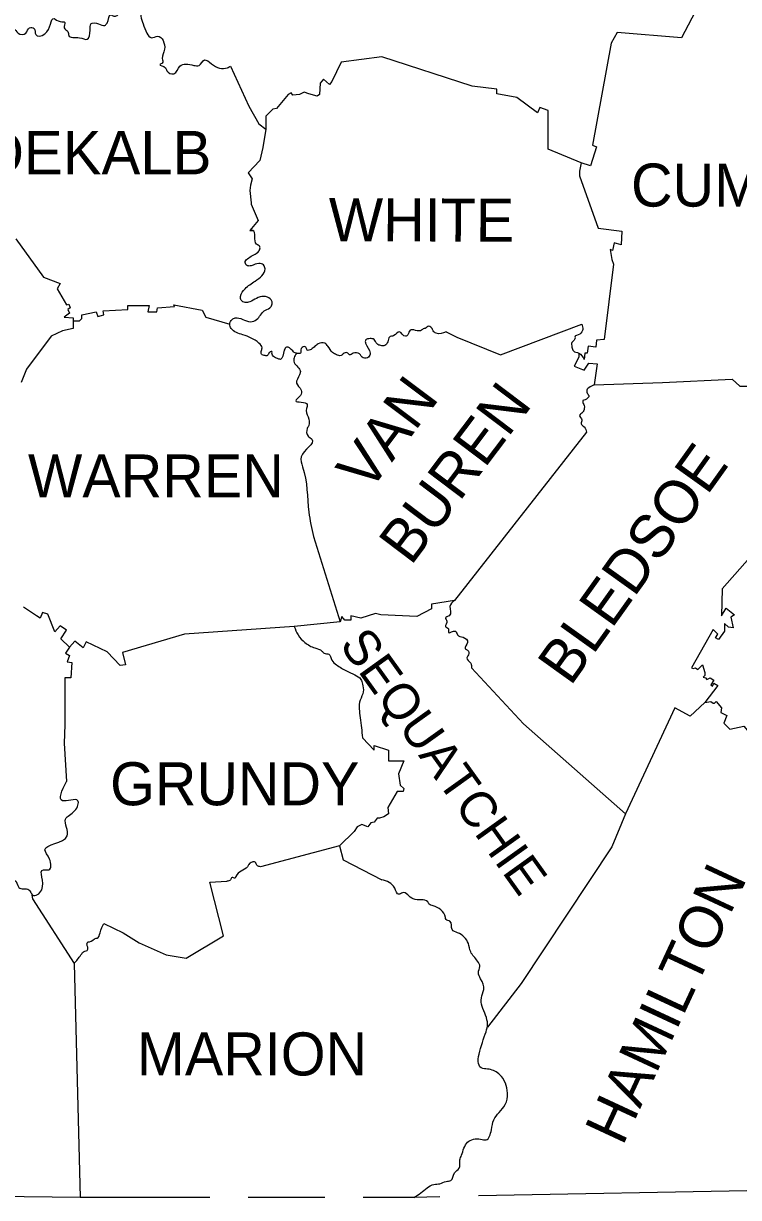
# Model space of a CAD drawing. Extents: x 1577619 to 1828281, y 483481 to 598136.
# Drawn here: x 1705140 to 1707004, y 529328 to 532387 of the extents above; entities that cross this region are included whole.
import ezdxf

# ---------------------------------------------------------------- set-up
doc = ezdxf.new("R2010")
doc.units = 0
doc.layers.add('DESIGN - SHEET - Corner Text', color=7, linetype='Continuous')
doc.layers.add('DESIGN - SHEET - Linework', color=7, linetype='Continuous')

msp = doc.modelspace()

# ---------------------------------------------------------------- linework, layer by layer
at = {"layer": 'DESIGN - SHEET - Linework'}
for p, q in [((1707176.2, 529347.6), (1706326.2, 529331.6)), ((1705926.2, 529327.6), (1705726.2, 529327.6))]:
    msp.add_line(p, q, dxfattribs=at)
for points in [[(1706900.2, 532433.6), (1706856.2, 532349.6), (1706688.2, 532363.6), (1706672.2, 532335.6), (1706624.2, 532069.6), (1706634.2, 532065.6), (1706618.2, 532015.6), (1706594.2, 532023.6), (1706508.2, 532059.6), (1706508.2, 532159.6), (1706486.2, 532167.6), (1706480.2, 532153.6), (1706426.2, 532193.6), (1706374.2, 532203.6), (1706374.2, 532215.6), (1706310.2, 532223.6), (1706074.2, 532299.6), (1705968.2, 532285.6), (1705944.2, 532235.6), (1705938.2, 532227.6), (1705922.2, 532241.6), (1705914.2, 532231.6), (1705912.2, 532201.6), (1705906.2, 532197.6), (1705884.2, 532203.6), (1705872.2, 532207.6), (1705860.2, 532201.6), (1705842.2, 532199.6), (1705838.2, 532205.6), (1705830.2, 532201.6), (1705800.2, 532165.6), (1705790.2, 532163.6), (1705772.2, 532145.6), (1705772.2, 532111.6), (1705764.2, 532063.6), (1705756.2, 532029.6), (1705726.2, 531997.6), (1705736.2, 531981.6), (1705732.2, 531965.6), (1705730.2, 531951.6), (1705734.2, 531919.6), (1705734.2, 531915.6), (1705752.2, 531873.6), (1705730.2, 531847.6), (1705738.2, 531847.6)], [(1705680.2, 532275.6), (1705728.2, 532171.6), (1705754.2, 532125.6), (1705772.2, 532111.6)], [(1706594.2, 532023.6), (1706590.2, 532001.6), (1706590.2, 531989.6), (1706638.2, 531853.6), (1706700.2, 531845.6), (1706698.2, 531809.6), (1706680.2, 531815.6), (1706676.2, 531795.6), (1706670.2, 531797.6), (1706674.2, 531771.6), (1706678.2, 531759.6), (1706654.2, 531563.6), (1706634.2, 531561.6), (1706632.2, 531543.6), (1706612.2, 531545.6), (1706610.2, 531527.6), (1706604.2, 531527.6), (1706602.2, 531511.6)], [(1705120.2, 531825.6), (1705192.2, 531725.6), (1705236.2, 531709.6), (1705228.2, 531695.6), (1705252.2, 531653.6), (1705258.2, 531655.6), (1705262.2, 531645.6), (1705256.2, 531641.6), (1705260.2, 531631.6), (1705246.2, 531621.6), (1705270.2, 531619.6), (1705270.2, 531591.6), (1705242.2, 531585.6), (1705212.2, 531571.6), (1705148.2, 531485.6), (1705134.2, 531451.6)], [(1705270.2, 531611.6), (1705286.2, 531611.6), (1705292.2, 531617.6), (1705292.2, 531627.6), (1705330.2, 531635.6), (1705334.2, 531623.6), (1705350.2, 531627.6), (1705348.2, 531637.6), (1705412.2, 531641.6), (1705412.2, 531651.6), (1705468.2, 531651.6), (1705464.2, 531635.6), (1705488.2, 531635.6), (1705490.2, 531645.6), (1705534.2, 531649.6), (1705532.2, 531653.6), (1705606.2, 531639.6), (1705616.2, 531621.6), (1705678.2, 531603.6)], [(1706242.2, 531583.6), (1706270.2, 531569.6), (1706384.2, 531523.6), (1706596.2, 531603.6)], [(1706588.2, 531525.6), (1706588.2, 531517.6), (1706576.2, 531493.6), (1706602.2, 531483.6), (1706614.2, 531501.6), (1706636.2, 531499.6), (1706628.2, 531445.6), (1706806.2, 531451.6), (1706988.2, 531459.6), (1707008.2, 531441.6), (1707038.2, 531441.6), (1707050.2, 531461.6), (1707098.2, 531461.6), (1707112.2, 531475.6), (1707130.2, 531431.6), (1707126.2, 531429.6), (1707132.2, 531399.6), (1707416.2, 531483.6), (1707456.2, 531495.6), (1707646.2, 531621.6), (1707654.2, 531625.6), (1707690.2, 531625.6)], [(1706608.2, 531321.6), (1706264.2, 530883.6)], [(1707126.2, 531099.6), (1706962.2, 530913.6), (1706960.2, 530843.6), (1706972.2, 530863.6), (1706994.2, 530845.6), (1706984.2, 530839.6), (1706990.2, 530811.6), (1706978.2, 530813.6), (1706968.2, 530823.6), (1706968.2, 530803.6), (1706952.2, 530781.6), (1706944.2, 530785.6), (1706950.2, 530795.6), (1706938.2, 530807.6), (1706882.2, 530707.6), (1706886.2, 530705.6), (1706892.2, 530707.6), (1706898.2, 530703.6), (1706910.2, 530715.6), (1706910.2, 530715.6), (1706916.2, 530695.6), (1706916.2, 530687.6), (1706912.2, 530683.6), (1706918.2, 530681.6), (1706922.2, 530677.6), (1706930.2, 530681.6), (1706940.2, 530675.6), (1706932.2, 530663.6), (1706936.2, 530659.6), (1706940.2, 530667.6), (1706950.2, 530661.6), (1706916.2, 530617.6), (1706878.2, 530581.6), (1706838.2, 530603.6), (1706710.2, 530327.6), (1706674.2, 530241.6), (1706438.2, 529885.6), (1706350.2, 529771.6)], [(1705896.2, 531049.6), (1705966.2, 530827.6)], [(1705260.2, 530761.6), (1705238.2, 530783.6), (1705252.2, 530805.6), (1705236.2, 530817.6), (1705222.2, 530801.6), (1705204.2, 530847.6), (1705190.2, 530851.6), (1705184.2, 530837.6), (1705174.2, 530843.6), (1705140.2, 530865.6)], [(1706264.2, 530883.6), (1706204.2, 530873.6), (1706204.2, 530861.6), (1706166.2, 530841.6), (1706072.2, 530845.6), (1706058.2, 530849.6), (1706020.2, 530837.6), (1705994.2, 530843.6), (1705994.2, 530831.6), (1705978.2, 530831.6), (1705970.2, 530841.6), (1705966.2, 530827.6), (1705846.2, 530815.6), (1705560.2, 530795.6), (1705398.2, 530747.6), (1705406.2, 530715.6), (1705392.2, 530713.6), (1705358.2, 530749.6), (1705304.2, 530775.6), (1705296.2, 530759.6), (1705274.2, 530777.6), (1705260.2, 530761.6), (1705250.2, 530745.6), (1705260.2, 530739.6), (1705254.2, 530723.6), (1705266.2, 530721.6), (1705264.2, 530681.6), (1705248.2, 530681.6), (1705248.2, 530559.6), (1705246.2, 530511.6), (1705252.2, 530411.6)], [(1706308.2, 530707.6), (1706444.2, 530561.6), (1706710.2, 530327.6)], [(1706916.2, 530617.6), (1706932.2, 530619.6), (1706938.2, 530615.6), (1706942.2, 530615.6), (1706946.2, 530619.6), (1706960.2, 530603.6), (1706958.2, 530591.6), (1706974.2, 530583.6), (1706966.2, 530563.6), (1706982.2, 530547.6), (1707018.2, 530555.6), (1707032.2, 530539.6), (1707028.2, 530531.6), (1707038.2, 530529.6), (1707040.2, 530539.6), (1707050.2, 530533.6), (1707066.2, 530551.6), (1707170.2, 530485.6)], [(1706024.2, 530525.6), (1706054.2, 530493.6), (1706054.2, 530505.6), (1706092.2, 530493.6), (1706092.2, 530465.6), (1706132.2, 530465.6), (1706118.2, 530431.6), (1706122.2, 530401.6), (1706132.2, 530393.6), (1706130.2, 530385.6), (1706114.2, 530385.6), (1706090.2, 530343.6), (1706092.2, 530327.6), (1706080.2, 530319.6), (1706068.2, 530315.6), (1706062.2, 530315.6), (1706054.2, 530305.6), (1706046.2, 530303.6), (1706038.2, 530293.6), (1706022.2, 530299.6), (1706010.2, 530293.6), (1706002.2, 530281.6), (1705964.2, 530243.6), (1705758.2, 530189.6)], [(1705964.2, 530243.6), (1705974.2, 530207.6), (1706074.2, 530155.6)], [(1705350.2, 530041.6), (1705400.2, 530017.6), (1705442.2, 529991.6), (1705512.2, 529959.6), (1705564.2, 529951.6), (1705662.2, 530009.6), (1705626.2, 530149.6), (1705670.2, 530151.6)], [(1705162.2, 530115.6), (1705164.2, 530105.6), (1705272.2, 529937.6), (1705288.2, 529327.6)], [(1705626.2, 529327.6), (1705288.2, 529327.6), (1704776.2, 529333.6)], [(1706226.2, 529329.6), (1706158.2, 529327.6), (1706026.2, 529327.6)]]:
    msp.add_lwpolyline(points, dxfattribs=at)
for points in [[(1704876.2, 532331.6), (1704882.2, 532337.6), (1704892.2, 532337.6), (1704918.2, 532321.6), (1704938.2, 532321.6), (1704952.2, 532321.6), (1704964.2, 532321.6), (1704980.2, 532317.6), (1704992.2, 532331.6), (1705004.2, 532315.6), (1705012.2, 532315.6), (1705024.2, 532331.6), (1705034.2, 532323.6), (1705066.2, 532343.6), (1705104.2, 532373.6), (1705114.2, 532373.6), (1705126.2, 532361.6), (1705146.2, 532361.6), (1705156.2, 532375.6), (1705168.2, 532373.6), (1705172.2, 532357.6), (1705196.2, 532359.6), (1705220.2, 532399.6), (1705236.2, 532391.6), (1705248.2, 532389.6), (1705246.2, 532375.6), (1705256.2, 532365.6), (1705258.2, 532355.6), (1705286.2, 532349.6), (1705306.2, 532345.6), (1705314.2, 532369.6), (1705316.2, 532385.6), (1705336.2, 532385.6), (1705352.2, 532381.6), (1705358.2, 532387.6), (1705368.2, 532409.6), (1705376.2, 532405.6), (1705384.2, 532407.6), (1705392.2, 532417.6), (1705410.2, 532429.6), (1705428.2, 532423.6), (1705444.2, 532415.6), (1705446.2, 532405.6), (1705452.2, 532385.6), (1705462.2, 532361.6), (1705474.2, 532349.6), (1705490.2, 532353.6), (1705508.2, 532319.6), (1705502.2, 532295.6), (1705502.2, 532283.6), (1705496.2, 532279.6), (1705510.2, 532271.6), (1705514.2, 532263.6), (1705532.2, 532255.6), (1705548.2, 532275.6), (1705584.2, 532277.6), (1705598.2, 532277.6), (1705612.2, 532291.6), (1705630.2, 532281.6), (1705672.2, 532271.6), (1705680.2, 532275.6)], [(1706242.2, 531583.6), (1706216.2, 531579.6), (1706208.2, 531585.6), (1706204.2, 531593.6), (1706194.2, 531597.6), (1706190.2, 531593.6), (1706180.2, 531589.6), (1706178.2, 531587.6), (1706148.2, 531587.6), (1706142.2, 531575.6), (1706136.2, 531571.6), (1706120.2, 531583.6), (1706106.2, 531573.6), (1706094.2, 531569.6), (1706090.2, 531557.6), (1706082.2, 531547.6), (1706072.2, 531547.6), (1706062.2, 531551.6), (1706054.2, 531563.6), (1706044.2, 531565.6), (1706032.2, 531561.6), (1706032.2, 531553.6), (1706044.2, 531527.6), (1706040.2, 531517.6), (1706026.2, 531515.6), (1706016.2, 531525.6), (1706000.2, 531527.6), (1705990.2, 531523.6), (1705986.2, 531527.6), (1705976.2, 531527.6), (1705968.2, 531521.6), (1705956.2, 531523.6), (1705946.2, 531529.6), (1705934.2, 531545.6), (1705926.2, 531553.6), (1705908.2, 531551.6), (1705900.2, 531545.6), (1705890.2, 531537.6), (1705880.2, 531535.6), (1705876.2, 531543.6), (1705864.2, 531539.6), (1705862.2, 531527.6), (1705852.2, 531527.6), (1705846.2, 531529.6), (1705842.2, 531533.6), (1705826.2, 531543.6), (1705820.2, 531535.6), (1705810.2, 531511.6), (1705802.2, 531513.6), (1705788.2, 531527.6), (1705788.2, 531531.6), (1705782.2, 531529.6), (1705776.2, 531521.6), (1705768.2, 531521.6), (1705762.2, 531523.6), (1705760.2, 531531.6), (1705762.2, 531541.6), (1705754.2, 531553.6), (1705712.2, 531575.6), (1705682.2, 531591.6), (1705678.2, 531603.6), (1705684.2, 531615.6), (1705692.2, 531619.6), (1705732.2, 531609.6), (1705748.2, 531615.6), (1705768.2, 531637.6), (1705782.2, 531645.6), (1705788.2, 531653.6), (1705788.2, 531663.6), (1705776.2, 531673.6), (1705766.2, 531675.6), (1705730.2, 531661.6), (1705718.2, 531659.6), (1705708.2, 531665.6), (1705706.2, 531675.6), (1705718.2, 531695.6), (1705744.2, 531715.6), (1705770.2, 531747.6), (1705766.2, 531757.6), (1705754.2, 531761.6), (1705734.2, 531755.6), (1705724.2, 531755.6), (1705718.2, 531763.6), (1705724.2, 531773.6), (1705750.2, 531789.6), (1705756.2, 531797.6), (1705756.2, 531805.6), (1705748.2, 531811.6), (1705738.2, 531847.6), (1705730.2, 531847.6)], [(1706596.2, 531603.6), (1706598.2, 531589.6), (1706596.2, 531583.6), (1706582.2, 531573.6), (1706578.2, 531571.6), (1706578.2, 531567.6), (1706574.2, 531559.6), (1706570.2, 531555.6), (1706570.2, 531543.6), (1706574.2, 531533.6), (1706588.2, 531527.6), (1706602.2, 531511.6)], [(1705852.2, 531527.6), (1705846.2, 531515.6), (1705846.2, 531503.6), (1705862.2, 531479.6), (1705860.2, 531471.6), (1705852.2, 531449.6), (1705864.2, 531431.6), (1705862.2, 531417.6), (1705850.2, 531403.6), (1705880.2, 531393.6), (1705878.2, 531383.6), (1705882.2, 531361.6), (1705884.2, 531339.6), (1705880.2, 531331.6), (1705882.2, 531311.6), (1705892.2, 531303.6), (1705864.2, 531257.6), (1705868.2, 531231.6), (1705884.2, 531113.6), (1705896.2, 531049.6)], [(1706628.2, 531445.6), (1706614.2, 531437.6), (1706610.2, 531433.6), (1706610.2, 531423.6), (1706614.2, 531415.6), (1706610.2, 531409.6), (1706602.2, 531405.6), (1706600.2, 531405.6), (1706598.2, 531401.6), (1706602.2, 531391.6), (1706602.2, 531383.6), (1706598.2, 531373.6), (1706590.2, 531365.6), (1706596.2, 531353.6), (1706594.2, 531343.6), (1706602.2, 531335.6), (1706608.2, 531321.6)], [(1706264.2, 530883.6), (1706252.2, 530867.6), (1706250.2, 530843.6), (1706240.2, 530837.6), (1706244.2, 530829.6), (1706240.2, 530815.6), (1706248.2, 530809.6), (1706248.2, 530799.6), (1706266.2, 530803.6), (1706272.2, 530793.6), (1706286.2, 530787.6), (1706298.2, 530773.6), (1706292.2, 530757.6), (1706298.2, 530753.6), (1706300.2, 530741.6), (1706296.2, 530733.6), (1706306.2, 530719.6), (1706308.2, 530707.6)], [(1705846.2, 530815.6), (1705856.2, 530793.6), (1705874.2, 530773.6), (1705900.2, 530759.6), (1705918.2, 530751.6), (1705924.2, 530745.6), (1705936.2, 530743.6), (1705944.2, 530727.6), (1705956.2, 530715.6), (1705982.2, 530699.6), (1706004.2, 530689.6), (1706020.2, 530677.6), (1706024.2, 530665.6), (1706026.2, 530645.6), (1706018.2, 530623.6), (1706018.2, 530577.6), (1706024.2, 530525.6)], [(1704910.2, 530267.6), (1704962.2, 530203.6), (1704978.2, 530213.6), (1704986.2, 530189.6), (1705008.2, 530191.6), (1705034.2, 530197.6), (1705036.2, 530183.6), (1705052.2, 530181.6), (1705058.2, 530185.6), (1705064.2, 530183.6), (1705066.2, 530157.6), (1705076.2, 530161.6), (1705088.2, 530175.6), (1705098.2, 530169.6), (1705098.2, 530157.6), (1705104.2, 530149.6), (1705118.2, 530153.6), (1705128.2, 530135.6), (1705154.2, 530129.6), (1705164.2, 530115.6), (1705188.2, 530129.6), (1705192.2, 530181.6), (1705206.2, 530181.6), (1705208.2, 530209.6), (1705196.2, 530233.6), (1705254.2, 530269.6), (1705250.2, 530313.6), (1705274.2, 530335.6), (1705282.2, 530361.6), (1705242.2, 530361.6), (1705252.2, 530411.6)], [(1705758.2, 530189.6), (1705750.2, 530191.6), (1705744.2, 530201.6), (1705736.2, 530201.6), (1705728.2, 530195.6), (1705724.2, 530189.6), (1705694.2, 530163.6), (1705692.2, 530159.6), (1705684.2, 530161.6), (1705680.2, 530155.6), (1705670.2, 530151.6)], [(1706158.2, 529327.6), (1706176.2, 529339.6), (1706210.2, 529361.6), (1706226.2, 529363.6), (1706242.2, 529369.6), (1706254.2, 529371.6), (1706264.2, 529391.6), (1706276.2, 529403.6), (1706278.2, 529425.6), (1706282.2, 529437.6), (1706298.2, 529471.6), (1706332.2, 529479.6), (1706346.2, 529477.6), (1706360.2, 529503.6), (1706366.2, 529529.6), (1706396.2, 529569.6), (1706402.2, 529599.6), (1706382.2, 529647.6), (1706354.2, 529661.6), (1706338.2, 529663.6), (1706346.2, 529759.6), (1706350.2, 529779.6), (1706336.2, 529825.6), (1706334.2, 529847.6), (1706340.2, 529869.6), (1706332.2, 529897.6), (1706326.2, 529913.6), (1706330.2, 529929.6), (1706324.2, 529943.6), (1706306.2, 529967.6), (1706300.2, 529989.6), (1706272.2, 530017.6), (1706258.2, 530025.6), (1706252.2, 530047.6), (1706242.2, 530051.6), (1706240.2, 530057.6), (1706208.2, 530087.6), (1706198.2, 530091.6), (1706194.2, 530097.6), (1706156.2, 530105.6), (1706128.2, 530121.6), (1706118.2, 530117.6), (1706108.2, 530133.6), (1706074.2, 530155.6)], [(1705272.2, 529937.6), (1705290.2, 529959.6), (1705300.2, 529969.6), (1705306.2, 529971.6), (1705308.2, 529977.6), (1705306.2, 529985.6), (1705308.2, 529993.6), (1705312.2, 529993.6), (1705330.2, 530003.6), (1705332.2, 530003.6), (1705340.2, 530017.6), (1705350.2, 530041.6)]]:
    msp.add_spline(points, degree=3, dxfattribs=at)

# ---------------------------------------------------------------- texts
at = {"layer": 'DESIGN - SHEET - Corner Text'}
for s, height, p in [('DEKALB', 113.36, (1705032.2, 531993.6)), ('CUMBERLAND', 112.16, (1706724.2, 531909.6)), ('WARREN', 112.16, (1705152.2, 531151.6)), ('GRUNDY', 112.16, (1705366.2, 530349.6)), ('MARION', 112.16, (1705436.2, 529645.6))]:
    msp.add_text(s, height=height, dxfattribs=at).set_placement(p)
for s, height, rotation, p in [('WHITE', 112.16, 359.7968, (1705936.2, 531819.6)), ('VAN', 112.93, 53.1301, (1706040.2, 531161.6)), ('BUREN', 112.93, 52.9269, (1706150.2, 530971.6)), ('BLEDSOE', 112.79, 54.3955, (1706566.2, 530657.6)), ('SEQUATCHIE', 93.34, 305.6229, (1705962.2, 530767.6)), ('HAMILTON', 111.72, 65.0587, (1706702.2, 529459.6))]:
    msp.add_text(s, height=height, rotation=rotation, dxfattribs=at).set_placement(p)

doc.saveas('drawing.dxf')
